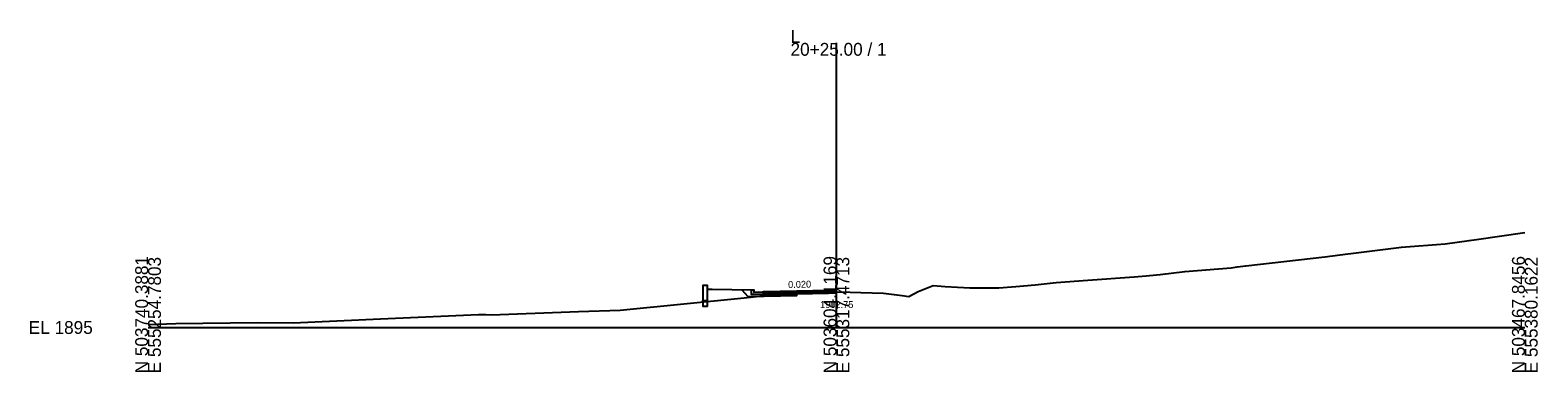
# Model space of a CAD drawing. Extents: x -26 to 4603, y -10 to 4703.
# Drawn here: x 4274.3 to 4602.8, y -9.7 to 64.9 of the extents above; entities that cross this region are included whole.
import ezdxf

# ---------------------------------------------------------------- set-up
doc = ezdxf.new("R2010")
doc.units = 0
doc.layers.add('Scratch_Level_1', color=7, linetype='Continuous')

msp = doc.modelspace()

# ---------------------------------------------------------------- linework, layer by layer
at = {"layer": 'Scratch_Level_1'}
for p, q in [((4450, 0), (4450, 62.13)), ((4300, 0), (4450, 0)), ((4450, 0), (4600, 0))]:
    msp.add_line(p, q, dxfattribs=at)
for points in [[(4300, 0.68), (4306.07, 0.86), (4323.74, 1.06), (4331.61, 1.02), (4350.66, 1.91), (4372.03, 2.86), (4373.61, 2.83), (4374.83, 2.77), (4393.79, 3.46), (4402.85, 3.81), (4429.86, 6.47), (4433.93, 6.89), (4434.65, 6.98), (4441.32, 7.59), (4442.4, 7.6), (4450, 7.75), (4450.7, 7.76), (4455.31, 7.64), (4460.22, 7.5), (4464.34, 7), (4465.79, 6.77), (4467.78, 7.84), (4471.07, 9.15), (4473.71, 8.98), (4479.08, 8.63), (4485.39, 8.69), (4489.07, 8.92), (4493.27, 9.34), (4497.85, 9.85), (4504.79, 10.34), (4514.9, 11.08), (4517.47, 11.28), (4518.24, 11.32), (4520.57, 11.59), (4525.9, 12.26), (4535.98, 13.04), (4537.35, 13.22), (4539.24, 13.46), (4556.43, 15.46), (4561.46, 16.07), (4562.08, 16.12), (4573.13, 17.57), (4582.62, 18.27), (4587.87, 19.02), (4589.48, 19.24), (4600, 20.71)], [(4421.89, 8.73), (4421.89, 9.18), (4421.79, 9.18), (4420.89, 9.18), (4420.89, 8.73), (4420.89, 4.67), (4421.79, 4.67), (4421.89, 4.67), (4421.89, 8.73)], [(4421.89, 8.38), (4422.93, 8.36), (4431.5, 8.19)], [(4429.36, 8.23), (4430.7, 6.79), (4441.34, 7), (4441.34, 7)], [(4433.8, 7.8), (4434, 7.81), (4434, 7.75), (4434, 7.23), (4433.75, 7.22), (4431.5, 7.18), (4431.5, 8.09), (4431.5, 8.19), (4431.95, 8.19), (4432, 8.19), (4432, 8.14), (4432, 7.69), (4433.8, 7.8)], [(4441.34, 7.96), (4434, 7.81), (4434, 7.56), (4434, 7.56), (4441.34, 7.71), (4441.34, 7.71), (4441.34, 7.71), (4441.34, 7.96), (4441.34, 7.96)], [(4441.34, 7.71), (4434, 7.56), (4434, 7.23), (4434, 7.23), (4441.34, 7.38), (4441.34, 7.38), (4441.34, 7.38), (4441.34, 7.71), (4441.34, 7.71)], [(4441.34, 7.38), (4434, 7.23), (4434, 6.85), (4434, 6.85), (4441.34, 7), (4441.34, 7), (4441.34, 7), (4441.34, 7.38), (4441.34, 7.38)], [(4448.28, 8.1), (4441.39, 7.96), (4441.39, 7.96), (4441.34, 7.96), (4441.34, 7.58), (4441.34, 7.58), (4441.39, 7.59), (4441.39, 7.59), (4448.28, 7.72), (4448.28, 7.72), (4450, 7.75), (4450, 7.75), (4450, 8.13), (4448.28, 8.1), (4448.28, 8.1)], [(4448.28, 7.85), (4441.39, 7.71), (4441.39, 7.71), (4441.34, 7.71), (4441.34, 7.38), (4441.34, 7.38), (4441.39, 7.38), (4441.39, 7.38), (4448.28, 7.51), (4448.28, 7.51), (4450, 7.55), (4450, 7.55), (4450, 7.88), (4448.28, 7.85), (4448.28, 7.85)], [(4450, 7.75), (4448.28, 7.72), (4448.28, 7.72), (4441.39, 7.59), (4441.39, 7.59), (4441.34, 7.58)], [(4420.89, 5.59), (4420.89, 5.87), (4420.89, 5.9), (4421.79, 5.92), (4421.89, 5.92)]]:
    msp.add_lwpolyline(points, dxfattribs=at)

# ---------------------------------------------------------------- texts
for s, height, p in [('L', 2.8, (4440, 62.13)), ('20+25.00 / 1', 2.8, (4440, 59.33)), ('X', 0.0025, (4421.89, 8.38)), ('X', 0.0025, (4422, 8.38)), ('X', 0.0025, (4422, 7.58)), ('X', 0.0025, (4422.5, 8.38)), ('X', 0.0025, (4427.5, 8.28)), ('X', 0.0025, (4432, 7.69)), ('X', 0.0025, (4434, 7.81)), ('X', 0.0025, (4450, 8.13)), ('X', 0.0025, (4420.87, 5.79)), ('1902.75', 1.5, (4446.44, 4.26)), ('EL 1895', 2.8, (4274, -1.4))]:
    msp.add_text(s, height=height, dxfattribs=at).set_placement(p)
for s, height, rotation, p in [('N 503740.3881', 2.8, 90, (4300, -10)), ('E 555254.7803', 2.8, 90, (4302.8, -10)), ('N 503604.1169', 2.8, 90, (4450, -10)), ('E 555317.4713', 2.8, 90, (4452.8, -10)), ('N 503467.8456', 2.8, 90, (4600, -10)), ('E 555380.1622', 2.8, 90, (4602.8, -10)), ('0.020', 1.5, 1.1458, (4439.48, 8.62))]:
    msp.add_text(s, height=height, rotation=rotation, dxfattribs=at).set_placement(p)

doc.saveas('drawing.dxf')
